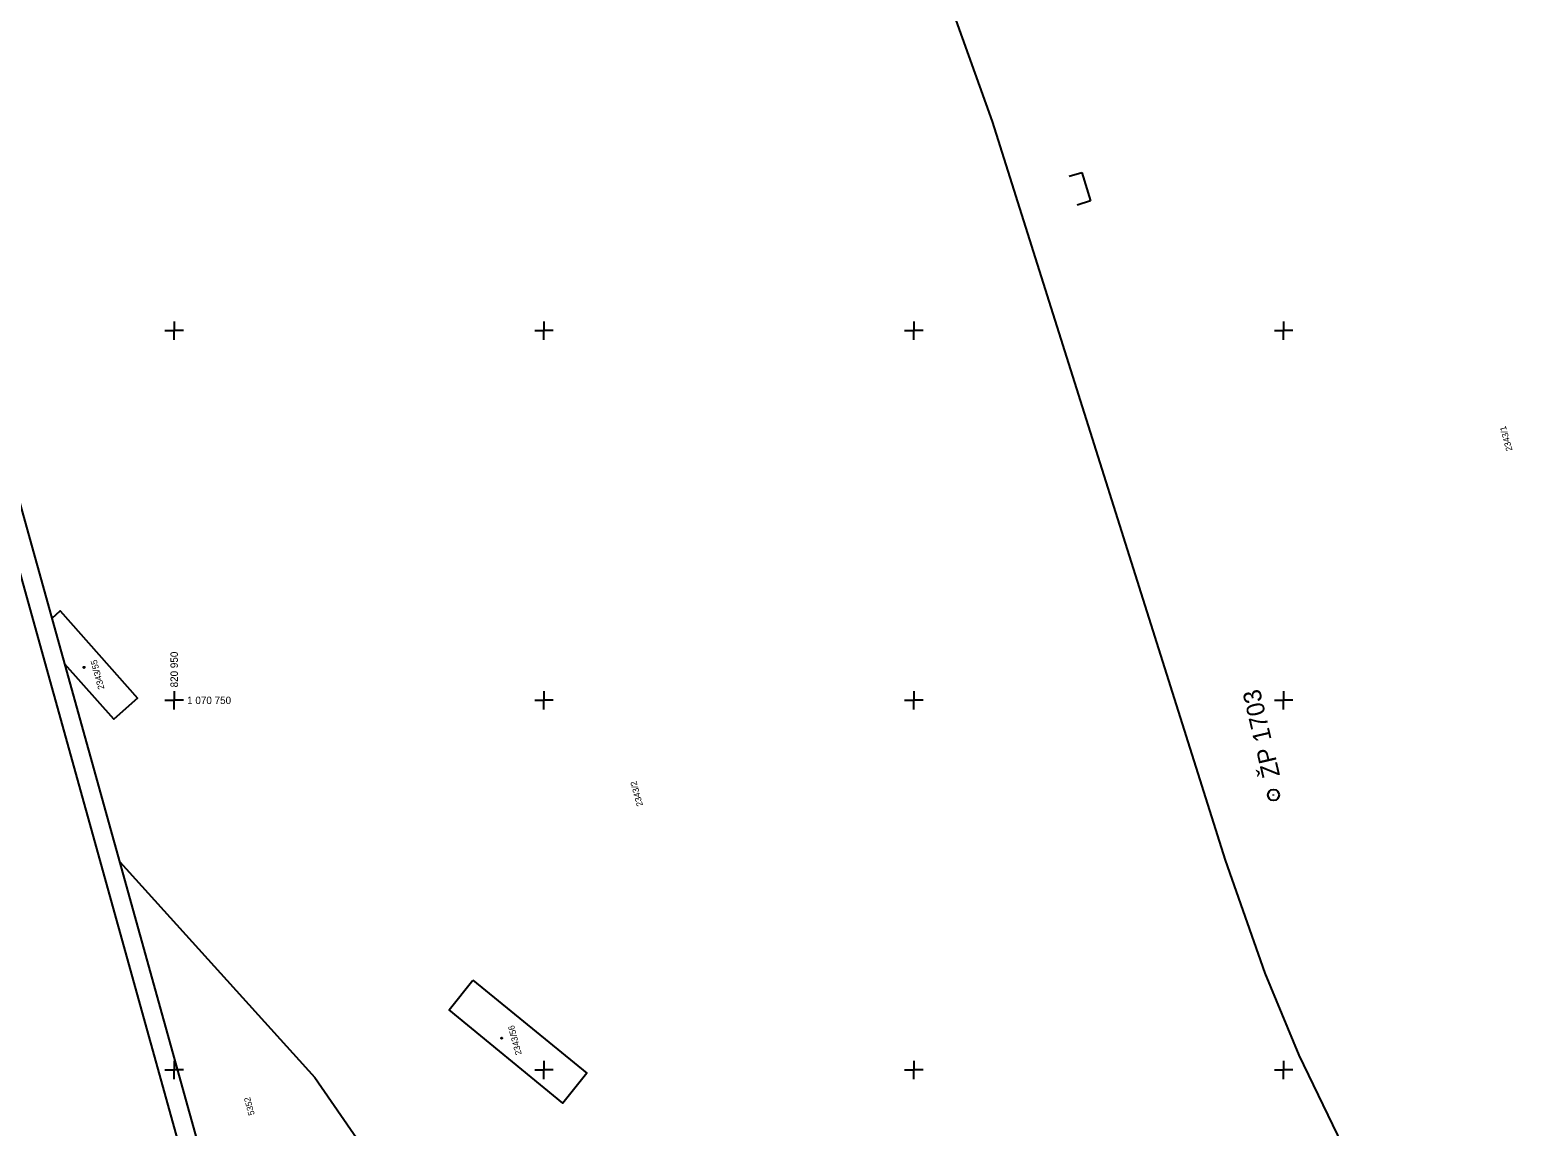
# Model space of a CAD drawing. Extents: x -821172 to -820632, y -1070921 to -1069931.
# Drawn here: x -820969.5 to -820765.6, y -1070807.7 to -1070659.4 of the extents above; entities that cross this region are included whole.
import ezdxf

# ---------------------------------------------------------------- set-up
doc = ezdxf.new("R2010")
doc.units = 0
for name, color, linetype in [('Ram', 7, 'Continuous'), ('Sit', 7, 'Continuous'), ('Vrstva 53', 7, 'Continuous'), ('Vrstva 55', 7, 'Continuous'), ('Vrstva 56', 7, 'Continuous'), ('Vrstva 57', 7, 'Continuous'), ('Vrstva 59', 7, 'Continuous'), ('ZBP', 7, 'Continuous')]:
    doc.layers.add(name, color=color, linetype=linetype)

msp = doc.modelspace()

# ---------------------------------------------------------------- linework, layer by layer
at = {"layer": 'Ram'}
for points in [[(-820775.54, -1070880.81), (-820918.62, -1070920.57), (-821143.51, -1070111.23)], [(-820916.88, -1070917.49), (-821140.43, -1070112.97)]]:
    msp.add_lwpolyline(points, dxfattribs=at)
at = {"layer": 'Sit'}
for p, q in [((-820951.25, -1070700), (-820950, -1070700)), ((-820950, -1070698.75), (-820950, -1070700)), ((-820948.75, -1070700), (-820950, -1070700)), ((-820950, -1070701.25), (-820950, -1070700)), ((-820901.25, -1070700), (-820900, -1070700)), ((-820900, -1070698.75), (-820900, -1070700)), ((-820898.75, -1070700), (-820900, -1070700)), ((-820900, -1070701.25), (-820900, -1070700)), ((-820851.25, -1070700), (-820850, -1070700)), ((-820850, -1070698.75), (-820850, -1070700)), ((-820848.75, -1070700), (-820850, -1070700)), ((-820850, -1070701.25), (-820850, -1070700)), ((-820801.25, -1070700), (-820800, -1070700)), ((-820800, -1070698.75), (-820800, -1070700)), ((-820798.75, -1070700), (-820800, -1070700)), ((-820800, -1070701.25), (-820800, -1070700)), ((-820950, -1070748.75), (-820950, -1070750)), ((-820900, -1070748.75), (-820900, -1070750)), ((-820850, -1070748.75), (-820850, -1070750)), ((-820800, -1070748.75), (-820800, -1070750)), ((-820951.25, -1070750), (-820950, -1070750)), ((-820948.75, -1070750), (-820950, -1070750)), ((-820950, -1070751.25), (-820950, -1070750)), ((-820901.25, -1070750), (-820900, -1070750)), ((-820898.75, -1070750), (-820900, -1070750)), ((-820900, -1070751.25), (-820900, -1070750)), ((-820851.25, -1070750), (-820850, -1070750)), ((-820848.75, -1070750), (-820850, -1070750)), ((-820850, -1070751.25), (-820850, -1070750)), ((-820801.25, -1070750), (-820800, -1070750)), ((-820798.75, -1070750), (-820800, -1070750)), ((-820800, -1070751.25), (-820800, -1070750)), ((-820950, -1070798.75), (-820950, -1070800)), ((-820900, -1070798.75), (-820900, -1070800)), ((-820850, -1070798.75), (-820850, -1070800)), ((-820800, -1070798.75), (-820800, -1070800)), ((-820951.25, -1070800), (-820950, -1070800)), ((-820948.75, -1070800), (-820950, -1070800)), ((-820950, -1070801.25), (-820950, -1070800)), ((-820901.25, -1070800), (-820900, -1070800)), ((-820898.75, -1070800), (-820900, -1070800)), ((-820900, -1070801.25), (-820900, -1070800)), ((-820851.25, -1070800), (-820850, -1070800)), ((-820848.75, -1070800), (-820850, -1070800)), ((-820850, -1070801.25), (-820850, -1070800)), ((-820801.25, -1070800), (-820800, -1070800)), ((-820798.75, -1070800), (-820800, -1070800)), ((-820800, -1070801.25), (-820800, -1070800))]:
    msp.add_line(p, q, dxfattribs=at)
at = {"layer": 'Vrstva 53'}
for points in [[(-820793.34, -1070807.43), (-820797.89, -1070798.01), (-820802.49, -1070786.9), (-820807.86, -1070771.6), (-820839.34, -1070671.73), (-820847.49, -1070649.05), (-820862.12, -1070611.55), (-820870.18, -1070588.9), (-820893.88, -1070513.71), (-820901.78, -1070488.65), (-820908.48, -1070465.88), (-820912.77, -1070441.75), (-820907.91, -1070440.8), (-820914.43, -1070404.83), (-820920.34, -1070372.85), (-820926.76, -1070341.17), (-820933.59, -1070313.73), (-820939.94, -1070294.5), (-820946.33, -1070279.59), (-820953.63, -1070265.09), (-820959.73, -1070254.91)], [(-820765.63, -1070875.45), (-820768.36, -1070867.01), (-820772.76, -1070853.45), (-820780.56, -1070834.55), (-820786.59, -1070821.38), (-820793.34, -1070807.43)]]:
    msp.add_lwpolyline(points, dxfattribs=at)
at = {"layer": 'Vrstva 55'}
for points in [[(-820793.34, -1070807.43), (-820797.89, -1070798.01), (-820802.49, -1070786.9), (-820807.86, -1070771.6), (-820839.34, -1070671.73), (-820847.49, -1070649.05), (-820862.12, -1070611.55), (-820870.18, -1070588.9), (-820893.88, -1070513.71), (-820901.78, -1070488.65), (-820908.48, -1070465.88), (-820912.77, -1070441.75), (-820907.91, -1070440.8), (-820914.43, -1070404.83), (-820920.34, -1070372.85), (-820926.76, -1070341.17), (-820933.59, -1070313.73), (-820939.94, -1070294.5), (-820946.33, -1070279.59), (-820953.63, -1070265.09), (-820959.73, -1070254.91)], [(-820966.51, -1070738.89), (-820965.4, -1070737.91), (-820954.94, -1070749.71), (-820958.16, -1070752.56), (-820964.78, -1070745.09)], [(-820957.35, -1070771.85), (-820930.99, -1070801.01), (-820892.18, -1070857.22), (-820885.9, -1070866.32)], [(-820909.62, -1070787.86), (-820894.2, -1070800.43), (-820897.46, -1070804.5), (-820912.83, -1070791.87), (-820909.62, -1070787.86)]]:
    msp.add_lwpolyline(points, dxfattribs=at)
at = {"layer": 'Vrstva 56'}
for p, q in [((-820828.99, -1070679.12), (-820827.3, -1070678.59)), ((-820827.3, -1070678.59), (-820826.1, -1070682.45)), ((-820826.1, -1070682.45), (-820827.91, -1070683.01))]:
    msp.add_line(p, q, dxfattribs=at)
at = {"layer": 'Vrstva 59'}
for centre in [(-820962.18, -1070745.55), (-820905.72, -1070795.69)]:
    msp.add_circle(centre, 0.0875, dxfattribs=at)
at = {"layer": 'ZBP'}
msp.add_line((-820801.36, -1070762.85), (-820801.38, -1070762.75), dxfattribs=at)
msp.add_circle((-820801.37, -1070762.8), 0.756, dxfattribs=at)

# ---------------------------------------------------------------- texts
at = {"layer": 'Sit'}
msp.add_text('820 950', height=1, rotation=90, dxfattribs=at).set_placement((-820949.5, -1070748.25))
msp.add_text('1 070 750', height=1, dxfattribs=at).set_placement((-820948.25, -1070750.5))
at = {"layer": 'Vrstva 57'}
for s, rotation, p in [('2343/1', 105.5289, (-820769.05, -1070716.17)), ('2343/55', 105, (-820959.42, -1070748.41)), ('2343/2', 105, (-820886.61, -1070764.21)), ('2343/56', 105, (-820903, -1070797.85)), ('5352', 105, (-820939.1, -1070806.02))]:
    msp.add_text(s, height=0.85, rotation=rotation, dxfattribs=at).set_placement(p)
at = {"layer": 'ZBP'}
msp.add_text('ŽP 1703', height=2.4, rotation=103.1745, dxfattribs=at).set_placement((-820800.47, -1070760.16))

doc.saveas('drawing.dxf')
